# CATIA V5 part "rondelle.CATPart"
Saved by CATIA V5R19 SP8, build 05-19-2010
Part number: rondelle percée
Bounding box of the stored display mesh (mm): x -2 to 5, y -25 to 25, z -24.818 to 24.818
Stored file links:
  G:\EU_thinkMotion\CFAO_2010\SIL_groupe1\SIL_groupe1\A reprendre\scador\monocycle\rondelle.CATPart
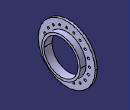
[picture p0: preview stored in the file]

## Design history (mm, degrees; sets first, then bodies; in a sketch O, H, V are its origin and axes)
Body1 (main body)
  Sketch1 on yz-plane, origin (0, 0, 0), H (0, 1, 0), V (0, 0, 1)
    circle A1 centre (0, 0) radius 15
    circle A2 centre (0, 0) radius 17
    distance O A1 = 15
    distance A2 A1 = 2
    concentricity: A1 A2
  Pad1: profile Sketch1, direction (1, 0, 0), length 5
  Sketch2 on yz-plane, origin (0, 0, 0), H (0, 1, 0), V (0, 0, 1)
    circle A1 centre (0, 0) radius 25
    circle A2 centre (0, 0) radius 15
    distance A2 A1 = 10
    distance O A2 = 15
    concentricity: A1 A2
  Pad2: profile Sketch2, direction (-1, 0, 0), length 2
  Sketch3 on end face of Pad2, origin (-2, 0, 20), H (0, 1, 0), V (0, 0, -1)
    point P1 (0, 0)
    reference projected circle E1 centre (0, 20) radius 25 from edge [end face of Pad2 | face of Pad2 from Sketch2.A1]
    reference projected point E2 (0, 0) from Sketch5
    reference projected circle E3 centre (0, 20) radius 25 from edge [end face of Pad2 | face of Pad2 from Sketch2.A1]
    distance E1 E2 = 5 (reference)
    distance P1 E3 = 5
  Hole1: placed by Sketch3, at (-2, 0, 20) direction (1, 0, 0), diameter 2, through (limit type 6)
  CircPattern1: of Hole1, instances 21, angular step 18, axis from end face of Pad2
  Sketch4 on start face of Pad2, origin (0, 0, 0), H (0, 1, 0), V (0, 0, 1)
    circle A1 centre (0, 0) radius 21
    point P1 (19.9722, 6.4894)
    point P2 (16.9894, 12.3435)
    point P3 (12.3435, 16.9894)
    point P4 (6.4894, 19.9722)
    point P5 (0, 21)
    point P6 (-6.4894, 19.9722)
    point P7 (-12.3435, 16.9894)
    point P8 (-16.9894, 12.3435)
    point P9 (-19.9722, 6.4894)
    point P10 (-21, 0)
    point P11 (-19.9722, -6.4894)
    point P12 (-16.9894, -12.3435)
    point P13 (-12.3435, -16.9894)
    point P14 (-6.4894, -19.9722)
    point P15 (0, -21)
    point P16 (6.4894, -19.9722)
    point P17 (12.3435, -16.9894)
    point P18 (16.9894, -12.3435)
    point P19 (19.9722, -6.4894)
    point P20 (21, 0)
    radius A1 = 21
    distance P1 P2 = 6.5702
    distance P2 P3 = 6.5702 {= Sketch4.distance(P1 P2)}
    distance P3 P4 = 6.5702 {= Sketch4.distance(P1 P2)}
    distance P4 P5 = 6.5702 {= Sketch4.distance(P1 P2)}
    distance P5 P6 = 6.5702 {= Sketch4.distance(P1 P2)}
    distance P6 P7 = 6.5702 {= Sketch4.distance(P1 P2)}
    distance P7 P8 = 6.5702 {= Sketch4.distance(P1 P2)}
    distance P8 P9 = 6.5702 {= Sketch4.distance(P1 P2)}
    distance P9 P10 = 6.5702 {= Sketch4.distance(P1 P2)}
    distance P10 P11 = 6.5702 {= Sketch4.distance(P1 P2)}
    distance P11 P12 = 6.5702 {= Sketch4.distance(P1 P2)}
    distance P12 P13 = 6.5702 {= Sketch4.distance(P1 P2)}
    distance P13 P14 = 6.5702 {= Sketch4.distance(P1 P2)}
    distance P14 P15 = 6.5702 {= Sketch4.distance(P1 P2)}
    distance P15 P16 = 6.5702 {= Sketch4.distance(P1 P2)}
    distance P16 P17 = 6.5702 {= Sketch4.distance(P1 P2)}
    distance P17 P18 = 6.5702 {= Sketch4.distance(P1 P2)}
    distance P18 P19 = 6.5702 {= Sketch4.distance(P1 P2)}
    distance P19 P20 = 6.5702 {= Sketch4.distance(P1 P2)}
    coincidence: A1 P1, A1 P2, A1 P3, A1 P4, A1 P5, A1 P6, A1 P7, A1 P8, A1 P9, A1 P10, A1 P11, A1 P12, A1 P13, A1 P14, A1 P15, A1 P16, A1 P17, A1 P18, A1 P19, A1 P20
  Sketch5 on end face of Pad2, origin (-2, 0, 0), H (0, -1, 0), V (0, 0, 1)
    point P1 (0, 20)
    distance P1 O = 20
    coincidence: P1 V
Relations
  Sketch4.distance(P1 P2) = Sketch4.distance(P1 P2) (deactivated)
